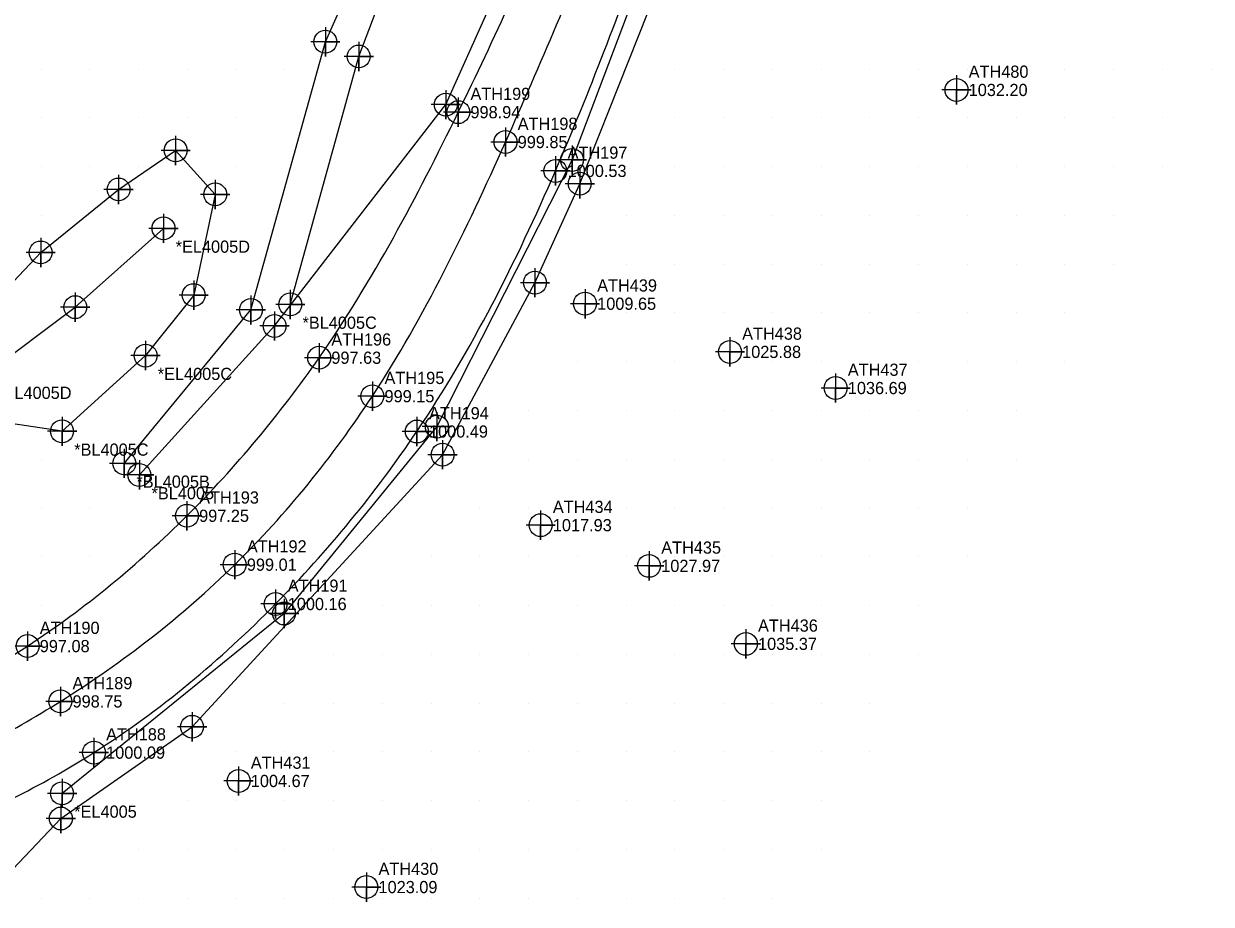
# Model space of a CAD drawing. Extents: x 1116680 to 1117499, y 661040 to 661703.
# Drawn here: x 1117186.4 to 1117430, y 661368.7 to 661549.3 of the extents above; entities that cross this region are included whole.
import ezdxf

# ---------------------------------------------------------------- set-up
doc = ezdxf.new("R2010")
doc.units = 0
for name, color, linetype in [('Exist DTM Breakline', 7, 'Continuous'), ('Exist DTM Breakline Cogo Comment', 7, 'Continuous'), ('Exist DTM Breakline Cogo Point CELL', 7, 'Continuous'), ('Exist DTM Crownline', 7, 'Continuous'), ('Exist DTM Crownline Cogo Elevation', 7, 'Continuous'), ('Exist DTM Crownline Cogo Number', 7, 'Continuous'), ('Exist DTM Crownline Cogo Point CELL', 7, 'Continuous'), ('Exist DTM QL2 LIDAR Elevation Point', 7, 'Continuous'), ('Exist DTM Regular Point CELL', 7, 'Continuous'), ('Exist DTM Regular Point Cogo Elevation', 7, 'Continuous'), ('Exist DTM Regular Point Cogo Number', 7, 'Continuous'), ('Exist Roads EOP', 7, 'Continuous'), ('Exist Roads EOP Cogo Elevation', 7, 'Continuous'), ('Exist Roads EOP Cogo Number', 7, 'Continuous'), ('Exist Roads EOP Cogo Point CELL', 7, 'Continuous')]:
    doc.layers.add(name, color=color, linetype=linetype)

msp = doc.modelspace()

# ---------------------------------------------------------------- linework, layer by layer
at = {"layer": 'Exist DTM Breakline'}
msp.add_line((1117194.27, 661465.73), (1117211.404, 661481.256), dxfattribs=at)
for points in [[(1117207.028, 661459.166), (1117233.018, 661490.613), (1117248.28, 661545.62), (1117268.093, 661590.069), (1117298.919, 661648.887), (1117319.378, 661676.709)], [(1117241.093, 661491.753), (1117255.131, 661542.605), (1117272.944, 661589.509), (1117306.544, 661644.722), (1117324.4, 661675.172)], [(1117210.127, 661456.793), (1117237.863, 661487.331), (1117272.992, 661532.718), (1117293.41, 661578.363), (1117331.106, 661672.763)], [(1117351.58, 661662.175), (1117339.299, 661629.132), (1117316.671, 661568.431), (1117298.876, 661521.377), (1117271.145, 661466.692), (1117239.817, 661428.377), (1117194.27, 661391.492)], [(1117161.696, 661291.017), (1117168.482, 661312.597), (1117176.266, 661342.559), (1117182.941, 661374.652), (1117194.026, 661386.336), (1117220.943, 661405.14), (1117272.33, 661460.939), (1117291.277, 661496.211), (1117300.472, 661516.498), (1117320.583, 661567.148), (1117342.592, 661626.703), (1117356.346, 661660.105)], [(1117194.27, 661465.73), (1117171.77, 661469.09), (1117169.6, 661480.945), (1117189.888, 661502.41), (1117205.863, 661515.329), (1117217.572, 661523.34), (1117225.692, 661514.312), (1117221.27, 661493.665), (1117211.404, 661481.256)], [(1117178.472, 661477.376), (1117196.976, 661491.194), (1117215.079, 661507.353)]]:
    msp.add_lwpolyline(points, dxfattribs=at)
at = {"layer": 'Exist DTM Breakline Cogo Point CELL'}
for points in [[(1117248.28, 661548.62), (1117248.28, 661542.62), (1117248.28, 661545.62), (1117251.28, 661545.62), (1117245.28, 661545.62)], [(1117255.131, 661545.605), (1117255.131, 661539.605), (1117255.131, 661542.605), (1117258.131, 661542.605), (1117252.131, 661542.605)], [(1117272.992, 661535.718), (1117272.992, 661529.718), (1117272.992, 661532.718), (1117275.992, 661532.718), (1117269.992, 661532.718)], [(1117217.572, 661526.34), (1117217.572, 661520.34), (1117217.572, 661523.34), (1117220.572, 661523.34), (1117214.572, 661523.34)], [(1117298.876, 661524.377), (1117298.876, 661518.377), (1117298.876, 661521.377), (1117301.876, 661521.377), (1117295.876, 661521.377)], [(1117205.863, 661518.329), (1117205.863, 661512.329), (1117205.863, 661515.329), (1117208.863, 661515.329), (1117202.863, 661515.329)], [(1117300.472, 661519.498), (1117300.472, 661513.498), (1117300.472, 661516.498), (1117303.472, 661516.498), (1117297.472, 661516.498)], [(1117225.692, 661517.312), (1117225.692, 661511.312), (1117225.692, 661514.312), (1117228.692, 661514.312), (1117222.692, 661514.312)], [(1117215.079, 661510.353), (1117215.079, 661504.353), (1117215.079, 661507.353), (1117218.079, 661507.353), (1117212.079, 661507.353)], [(1117189.888, 661505.41), (1117189.888, 661499.41), (1117189.888, 661502.41), (1117192.888, 661502.41), (1117186.888, 661502.41)], [(1117291.277, 661499.211), (1117291.277, 661493.211), (1117291.277, 661496.211), (1117294.277, 661496.211), (1117288.277, 661496.211)], [(1117221.27, 661496.665), (1117221.27, 661490.665), (1117221.27, 661493.665), (1117224.27, 661493.665), (1117218.27, 661493.665)], [(1117196.976, 661494.194), (1117196.976, 661488.194), (1117196.976, 661491.194), (1117199.976, 661491.194), (1117193.976, 661491.194)], [(1117233.018, 661493.613), (1117233.018, 661487.613), (1117233.018, 661490.613), (1117236.018, 661490.613), (1117230.018, 661490.613)], [(1117241.093, 661494.753), (1117241.093, 661488.753), (1117241.093, 661491.753), (1117244.093, 661491.753), (1117238.093, 661491.753)], [(1117237.863, 661490.331), (1117237.863, 661484.331), (1117237.863, 661487.331), (1117240.863, 661487.331), (1117234.863, 661487.331)], [(1117211.404, 661484.256), (1117211.404, 661478.256), (1117211.404, 661481.256), (1117214.404, 661481.256), (1117208.404, 661481.256)], [(1117194.27, 661468.73), (1117194.27, 661462.73), (1117194.27, 661465.73), (1117197.27, 661465.73), (1117191.27, 661465.73)], [(1117271.145, 661469.692), (1117271.145, 661463.692), (1117271.145, 661466.692), (1117274.145, 661466.692), (1117268.145, 661466.692)], [(1117272.33, 661463.939), (1117272.33, 661457.939), (1117272.33, 661460.939), (1117275.33, 661460.939), (1117269.33, 661460.939)], [(1117207.028, 661462.166), (1117207.028, 661456.166), (1117207.028, 661459.166), (1117210.028, 661459.166), (1117204.028, 661459.166)], [(1117210.127, 661459.793), (1117210.127, 661453.793), (1117210.127, 661456.793), (1117213.127, 661456.793), (1117207.127, 661456.793)], [(1117239.817, 661431.377), (1117239.817, 661425.377), (1117239.817, 661428.377), (1117242.817, 661428.377), (1117236.817, 661428.377)], [(1117220.943, 661408.14), (1117220.943, 661402.14), (1117220.943, 661405.14), (1117223.943, 661405.14), (1117217.943, 661405.14)], [(1117194.27, 661394.492), (1117194.27, 661388.492), (1117194.27, 661391.492), (1117197.27, 661391.492), (1117191.27, 661391.492)], [(1117194.026, 661389.336), (1117194.026, 661383.336), (1117194.026, 661386.336), (1117197.026, 661386.336), (1117191.026, 661386.336)]]:
    msp.add_lwpolyline(points, dxfattribs=at)
for centre in [(1117248.28, 661545.62), (1117255.131, 661542.605), (1117272.992, 661532.718), (1117217.572, 661523.34), (1117298.876, 661521.377), (1117205.863, 661515.329), (1117300.472, 661516.498), (1117225.692, 661514.312), (1117215.079, 661507.353), (1117189.888, 661502.41), (1117291.277, 661496.211), (1117221.27, 661493.665), (1117196.976, 661491.194), (1117241.093, 661491.753), (1117233.018, 661490.613), (1117237.863, 661487.331), (1117211.404, 661481.256), (1117271.145, 661466.692), (1117194.27, 661465.73), (1117207.028, 661459.166), (1117272.33, 661460.939), (1117210.127, 661456.793), (1117239.817, 661428.377), (1117220.943, 661405.14), (1117194.27, 661391.492), (1117194.026, 661386.336)]:
    msp.add_circle(centre, 2.344, dxfattribs=at)
at = {"layer": 'Exist DTM Crownline'}
msp.add_spline([(1117128.608, 661382.881), (1117161.083, 661393.544), (1117193.928, 661410.345), (1117229.679, 661438.384), (1117257.918, 661472.931), (1117285.234, 661525.056), (1117305.735, 661573.245), (1117329.129, 661633.315)], degree=3, dxfattribs=at)
at = {"layer": 'Exist DTM Crownline Cogo Point CELL'}
for points in [[(1117285.234, 661528.056), (1117285.234, 661522.056), (1117285.234, 661525.056), (1117288.234, 661525.056), (1117282.234, 661525.056)], [(1117257.918, 661475.931), (1117257.918, 661469.931), (1117257.918, 661472.931), (1117260.918, 661472.931), (1117254.918, 661472.931)], [(1117229.679, 661441.384), (1117229.679, 661435.384), (1117229.679, 661438.384), (1117232.679, 661438.384), (1117226.679, 661438.384)], [(1117193.928, 661413.345), (1117193.928, 661407.345), (1117193.928, 661410.345), (1117196.928, 661410.345), (1117190.928, 661410.345)]]:
    msp.add_lwpolyline(points, dxfattribs=at)
for centre in [(1117285.234, 661525.056), (1117257.918, 661472.931), (1117229.679, 661438.384), (1117193.928, 661410.345)]:
    msp.add_circle(centre, 2.344, dxfattribs=at)
at = {"layer": 'Exist DTM QL2 LIDAR Elevation Point'}
for p, q in [((1117190, 661540), (1117190, 661540)), ((1117200, 661540), (1117200, 661540)), ((1117210, 661540), (1117210, 661540)), ((1117220, 661540), (1117220, 661540)), ((1117230, 661540), (1117230, 661540)), ((1117240, 661540), (1117240, 661540)), ((1117320, 661540), (1117320, 661540)), ((1117330, 661540), (1117330, 661540)), ((1117340, 661540), (1117340, 661540)), ((1117350, 661540), (1117350, 661540)), ((1117360, 661540), (1117360, 661540)), ((1117370, 661540), (1117370, 661540)), ((1117380, 661540), (1117380, 661540)), ((1117390, 661540), (1117390, 661540)), ((1117400, 661540), (1117400, 661540)), ((1117410, 661540), (1117410, 661540)), ((1117420, 661540), (1117420, 661540)), ((1117430, 661540), (1117430, 661540)), ((1117190, 661530), (1117190, 661530)), ((1117200, 661530), (1117200, 661530)), ((1117210, 661530), (1117210, 661530)), ((1117220, 661530), (1117220, 661530)), ((1117230, 661530), (1117230, 661530)), ((1117320, 661530), (1117320, 661530)), ((1117330, 661530), (1117330, 661530)), ((1117340, 661530), (1117340, 661530)), ((1117350, 661530), (1117350, 661530)), ((1117360, 661530), (1117360, 661530)), ((1117370, 661530), (1117370, 661530)), ((1117380, 661530), (1117380, 661530)), ((1117390, 661530), (1117390, 661530)), ((1117400, 661530), (1117400, 661530)), ((1117410, 661530), (1117410, 661530)), ((1117420, 661530), (1117420, 661530)), ((1117190, 661520), (1117190, 661520)), ((1117200, 661520), (1117200, 661520)), ((1117210, 661520), (1117210, 661520)), ((1117230, 661520), (1117230, 661520)), ((1117310, 661520), (1117310, 661520)), ((1117320, 661520), (1117320, 661520)), ((1117330, 661520), (1117330, 661520)), ((1117340, 661520), (1117340, 661520)), ((1117350, 661520), (1117350, 661520)), ((1117360, 661520), (1117360, 661520)), ((1117370, 661520), (1117370, 661520)), ((1117380, 661520), (1117380, 661520)), ((1117390, 661520), (1117390, 661520)), ((1117400, 661520), (1117400, 661520)), ((1117410, 661520), (1117410, 661520)), ((1117420, 661520), (1117420, 661520)), ((1117190, 661510), (1117190, 661510)), ((1117310, 661510), (1117310, 661510)), ((1117320, 661510), (1117320, 661510)), ((1117330, 661510), (1117330, 661510)), ((1117340, 661510), (1117340, 661510)), ((1117350, 661510), (1117350, 661510)), ((1117360, 661510), (1117360, 661510)), ((1117370, 661510), (1117370, 661510)), ((1117380, 661510), (1117380, 661510)), ((1117390, 661510), (1117390, 661510)), ((1117400, 661510), (1117400, 661510)), ((1117410, 661510), (1117410, 661510)), ((1117310, 661500), (1117310, 661500)), ((1117320, 661500), (1117320, 661500)), ((1117330, 661500), (1117330, 661500)), ((1117340, 661500), (1117340, 661500)), ((1117350, 661500), (1117350, 661500)), ((1117360, 661500), (1117360, 661500)), ((1117370, 661500), (1117370, 661500)), ((1117380, 661500), (1117380, 661500)), ((1117390, 661500), (1117390, 661500)), ((1117400, 661500), (1117400, 661500)), ((1117410, 661500), (1117410, 661500)), ((1117310, 661490), (1117310, 661490)), ((1117320, 661490), (1117320, 661490)), ((1117330, 661490), (1117330, 661490)), ((1117340, 661490), (1117340, 661490)), ((1117350, 661490), (1117350, 661490)), ((1117360, 661490), (1117360, 661490)), ((1117370, 661490), (1117370, 661490)), ((1117380, 661490), (1117380, 661490)), ((1117390, 661490), (1117390, 661490)), ((1117400, 661490), (1117400, 661490)), ((1117300, 661480), (1117300, 661480)), ((1117310, 661480), (1117310, 661480)), ((1117320, 661480), (1117320, 661480)), ((1117330, 661480), (1117330, 661480)), ((1117340, 661480), (1117340, 661480)), ((1117350, 661480), (1117350, 661480)), ((1117360, 661480), (1117360, 661480)), ((1117370, 661480), (1117370, 661480)), ((1117380, 661480), (1117380, 661480)), ((1117390, 661480), (1117390, 661480)), ((1117400, 661480), (1117400, 661480)), ((1117290, 661470), (1117290, 661470)), ((1117300, 661470), (1117300, 661470)), ((1117310, 661470), (1117310, 661470)), ((1117320, 661470), (1117320, 661470)), ((1117330, 661470), (1117330, 661470)), ((1117340, 661470), (1117340, 661470)), ((1117350, 661470), (1117350, 661470)), ((1117360, 661470), (1117360, 661470)), ((1117370, 661470), (1117370, 661470)), ((1117380, 661470), (1117380, 661470)), ((1117390, 661470), (1117390, 661470)), ((1117190, 661460), (1117190, 661460)), ((1117290, 661460), (1117290, 661460)), ((1117300, 661460), (1117300, 661460)), ((1117310, 661460), (1117310, 661460)), ((1117320, 661460), (1117320, 661460)), ((1117330, 661460), (1117330, 661460)), ((1117340, 661460), (1117340, 661460)), ((1117350, 661460), (1117350, 661460)), ((1117360, 661460), (1117360, 661460)), ((1117370, 661460), (1117370, 661460)), ((1117380, 661460), (1117380, 661460)), ((1117390, 661460), (1117390, 661460)), ((1117190, 661450), (1117190, 661450)), ((1117200, 661450), (1117200, 661450)), ((1117280, 661450), (1117280, 661450)), ((1117290, 661450), (1117290, 661450)), ((1117300, 661450), (1117300, 661450)), ((1117310, 661450), (1117310, 661450)), ((1117320, 661450), (1117320, 661450)), ((1117330, 661450), (1117330, 661450)), ((1117340, 661450), (1117340, 661450)), ((1117350, 661450), (1117350, 661450)), ((1117360, 661450), (1117360, 661450)), ((1117370, 661450), (1117370, 661450)), ((1117380, 661450), (1117380, 661450)), ((1117190, 661440), (1117190, 661440)), ((1117200, 661440), (1117200, 661440)), ((1117270, 661440), (1117270, 661440)), ((1117280, 661440), (1117280, 661440)), ((1117290, 661440), (1117290, 661440)), ((1117300, 661440), (1117300, 661440)), ((1117310, 661440), (1117310, 661440)), ((1117320, 661440), (1117320, 661440)), ((1117330, 661440), (1117330, 661440)), ((1117340, 661440), (1117340, 661440)), ((1117350, 661440), (1117350, 661440)), ((1117360, 661440), (1117360, 661440)), ((1117370, 661440), (1117370, 661440)), ((1117380, 661440), (1117380, 661440)), ((1117190, 661430), (1117190, 661430)), ((1117260, 661430), (1117260, 661430)), ((1117270, 661430), (1117270, 661430)), ((1117280, 661430), (1117280, 661430)), ((1117290, 661430), (1117290, 661430)), ((1117300, 661430), (1117300, 661430)), ((1117310, 661430), (1117310, 661430)), ((1117320, 661430), (1117320, 661430)), ((1117330, 661430), (1117330, 661430)), ((1117340, 661430), (1117340, 661430)), ((1117350, 661430), (1117350, 661430)), ((1117360, 661430), (1117360, 661430)), ((1117370, 661430), (1117370, 661430)), ((1117250, 661420), (1117250, 661420)), ((1117260, 661420), (1117260, 661420)), ((1117270, 661420), (1117270, 661420)), ((1117280, 661420), (1117280, 661420)), ((1117290, 661420), (1117290, 661420)), ((1117300, 661420), (1117300, 661420)), ((1117310, 661420), (1117310, 661420)), ((1117320, 661420), (1117320, 661420)), ((1117330, 661420), (1117330, 661420)), ((1117340, 661420), (1117340, 661420)), ((1117350, 661420), (1117350, 661420)), ((1117360, 661420), (1117360, 661420)), ((1117370, 661420), (1117370, 661420)), ((1117240, 661410), (1117240, 661410)), ((1117250, 661410), (1117250, 661410)), ((1117260, 661410), (1117260, 661410)), ((1117270, 661410), (1117270, 661410)), ((1117280, 661410), (1117280, 661410)), ((1117290, 661410), (1117290, 661410)), ((1117300, 661410), (1117300, 661410)), ((1117310, 661410), (1117310, 661410)), ((1117320, 661410), (1117320, 661410)), ((1117330, 661410), (1117330, 661410)), ((1117340, 661410), (1117340, 661410)), ((1117350, 661410), (1117350, 661410)), ((1117360, 661410), (1117360, 661410)), ((1117230, 661400), (1117230, 661400)), ((1117240, 661400), (1117240, 661400)), ((1117250, 661400), (1117250, 661400)), ((1117260, 661400), (1117260, 661400)), ((1117270, 661400), (1117270, 661400)), ((1117280, 661400), (1117280, 661400)), ((1117290, 661400), (1117290, 661400)), ((1117300, 661400), (1117300, 661400)), ((1117310, 661400), (1117310, 661400)), ((1117320, 661400), (1117320, 661400)), ((1117330, 661400), (1117330, 661400)), ((1117340, 661400), (1117340, 661400)), ((1117350, 661400), (1117350, 661400)), ((1117360, 661400), (1117360, 661400)), ((1117220, 661390), (1117220, 661390)), ((1117230, 661390), (1117230, 661390)), ((1117240, 661390), (1117240, 661390)), ((1117250, 661390), (1117250, 661390)), ((1117260, 661390), (1117260, 661390)), ((1117270, 661390), (1117270, 661390)), ((1117280, 661390), (1117280, 661390)), ((1117290, 661390), (1117290, 661390)), ((1117300, 661390), (1117300, 661390)), ((1117310, 661390), (1117310, 661390)), ((1117320, 661390), (1117320, 661390)), ((1117330, 661390), (1117330, 661390)), ((1117340, 661390), (1117340, 661390)), ((1117350, 661390), (1117350, 661390)), ((1117210, 661380), (1117210, 661380)), ((1117220, 661380), (1117220, 661380)), ((1117230, 661380), (1117230, 661380)), ((1117240, 661380), (1117240, 661380)), ((1117250, 661380), (1117250, 661380)), ((1117260, 661380), (1117260, 661380)), ((1117270, 661380), (1117270, 661380)), ((1117280, 661380), (1117280, 661380)), ((1117290, 661380), (1117290, 661380)), ((1117300, 661380), (1117300, 661380)), ((1117310, 661380), (1117310, 661380)), ((1117320, 661380), (1117320, 661380)), ((1117330, 661380), (1117330, 661380)), ((1117340, 661380), (1117340, 661380)), ((1117350, 661380), (1117350, 661380)), ((1117190, 661370), (1117190, 661370)), ((1117200, 661370), (1117200, 661370)), ((1117210, 661370), (1117210, 661370)), ((1117220, 661370), (1117220, 661370)), ((1117230, 661370), (1117230, 661370)), ((1117240, 661370), (1117240, 661370)), ((1117250, 661370), (1117250, 661370)), ((1117260, 661370), (1117260, 661370)), ((1117270, 661370), (1117270, 661370)), ((1117280, 661370), (1117280, 661370)), ((1117290, 661370), (1117290, 661370)), ((1117300, 661370), (1117300, 661370)), ((1117310, 661370), (1117310, 661370)), ((1117320, 661370), (1117320, 661370)), ((1117330, 661370), (1117330, 661370)), ((1117340, 661370), (1117340, 661370))]:
    msp.add_line(p, q, dxfattribs=at)
at = {"layer": 'Exist DTM Regular Point CELL'}
for points in [[(1117377.744, 661538.736), (1117377.744, 661532.736), (1117377.744, 661535.736), (1117380.744, 661535.736), (1117374.744, 661535.736)], [(1117301.542, 661494.899), (1117301.542, 661488.899), (1117301.542, 661491.899), (1117304.542, 661491.899), (1117298.542, 661491.899)], [(1117331.279, 661485.017), (1117331.279, 661479.017), (1117331.279, 661482.017), (1117334.279, 661482.017), (1117328.279, 661482.017)], [(1117352.951, 661477.61), (1117352.951, 661471.61), (1117352.951, 661474.61), (1117355.951, 661474.61), (1117349.951, 661474.61)], [(1117292.445, 661449.487), (1117292.445, 661443.487), (1117292.445, 661446.487), (1117295.445, 661446.487), (1117289.445, 661446.487)], [(1117314.679, 661441.139), (1117314.679, 661435.139), (1117314.679, 661438.139), (1117317.679, 661438.139), (1117311.679, 661438.139)], [(1117334.535, 661425.143), (1117334.535, 661419.143), (1117334.535, 661422.143), (1117337.535, 661422.143), (1117331.535, 661422.143)], [(1117230.487, 661397.029), (1117230.487, 661391.029), (1117230.487, 661394.029), (1117233.487, 661394.029), (1117227.487, 661394.029)], [(1117256.688, 661375.272), (1117256.688, 661369.272), (1117256.688, 661372.272), (1117259.688, 661372.272), (1117253.688, 661372.272)]]:
    msp.add_lwpolyline(points, dxfattribs=at)
for centre in [(1117377.744, 661535.736), (1117301.542, 661491.899), (1117331.279, 661482.017), (1117352.951, 661474.61), (1117292.445, 661446.487), (1117314.679, 661438.139), (1117334.535, 661422.143), (1117230.487, 661394.029), (1117256.688, 661372.272)]:
    msp.add_circle(centre, 2.344, dxfattribs=at)
at = {"layer": 'Exist Roads EOP'}
for points in [[(1117102.286, 661387.333), (1117126.621, 661394.057), (1117156.418, 661404.979), (1117187.204, 661421.689), (1117219.891, 661448.41), (1117247.012, 661480.823), (1117275.546, 661531.18), (1117296.661, 661577.27), (1117320.803, 661635.676)], [(1117131.334, 661372.856), (1117166.321, 661382.847), (1117200.815, 661399.841), (1117238.067, 661430.322), (1117267.048, 661465.689), (1117295.472, 661519.132), (1117314.821, 661568.418)]]:
    msp.add_spline(points, degree=3, dxfattribs=at)
at = {"layer": 'Exist Roads EOP Cogo Point CELL'}
for points in [[(1117275.546, 661534.18), (1117275.546, 661528.18), (1117275.546, 661531.18), (1117278.546, 661531.18), (1117272.546, 661531.18)], [(1117295.472, 661522.132), (1117295.472, 661516.132), (1117295.472, 661519.132), (1117298.472, 661519.132), (1117292.472, 661519.132)], [(1117247.012, 661483.823), (1117247.012, 661477.823), (1117247.012, 661480.823), (1117250.012, 661480.823), (1117244.012, 661480.823)], [(1117267.048, 661468.689), (1117267.048, 661462.689), (1117267.048, 661465.689), (1117270.048, 661465.689), (1117264.048, 661465.689)], [(1117219.891, 661451.41), (1117219.891, 661445.41), (1117219.891, 661448.41), (1117222.891, 661448.41), (1117216.891, 661448.41)], [(1117238.067, 661433.322), (1117238.067, 661427.322), (1117238.067, 661430.322), (1117241.067, 661430.322), (1117235.067, 661430.322)], [(1117187.204, 661424.689), (1117187.204, 661418.689), (1117187.204, 661421.689), (1117190.204, 661421.689), (1117184.204, 661421.689)], [(1117200.815, 661402.841), (1117200.815, 661396.841), (1117200.815, 661399.841), (1117203.815, 661399.841), (1117197.815, 661399.841)]]:
    msp.add_lwpolyline(points, dxfattribs=at)
for centre in [(1117275.546, 661531.18), (1117295.472, 661519.132), (1117247.012, 661480.823), (1117267.048, 661465.689), (1117219.891, 661448.41), (1117238.067, 661430.322), (1117187.204, 661421.689), (1117200.815, 661399.841)]:
    msp.add_circle(centre, 2.344, dxfattribs=at)

# ---------------------------------------------------------------- texts
at = {"layer": 'Exist DTM Breakline Cogo Comment'}
for s, p in [('*EL4005D', (1117217.579, 661502.353)), ('*BL4005C', (1117243.593, 661486.753)), ('*EL4005C', (1117213.904, 661476.256)), ('*BL4005D', (1117180.972, 661472.376)), ('*BL4005C', (1117196.77, 661460.73)), ('*BL4005B', (1117209.528, 661454.166)), ('*BL4005', (1117212.627, 661451.793)), ('*EL4005', (1117196.77, 661386.492))]:
    msp.add_text(s, height=2.5, dxfattribs=at).set_placement(p)
at = {"layer": 'Exist DTM Crownline Cogo Elevation'}
for s, p in [('999.85', (1117287.734, 661523.806)), ('999.15', (1117260.418, 661471.681)), ('999.01', (1117232.179, 661437.134)), ('998.75', (1117196.428, 661409.095))]:
    msp.add_text(s, height=2.5, dxfattribs=at).set_placement(p)
at = {"layer": 'Exist DTM Crownline Cogo Number'}
for s, p in [('ATH198', (1117287.734, 661527.556)), ('ATH195', (1117260.418, 661475.431)), ('ATH192', (1117232.179, 661440.884)), ('ATH189', (1117196.428, 661412.845))]:
    msp.add_text(s, height=2.5, dxfattribs=at).set_placement(p)
at = {"layer": 'Exist DTM Regular Point Cogo Elevation'}
for s, p in [('1032.20', (1117380.244, 661534.486)), ('1009.65', (1117304.042, 661490.649)), ('1025.88', (1117333.779, 661480.767)), ('1036.69', (1117355.451, 661473.36)), ('1017.93', (1117294.945, 661445.237)), ('1027.97', (1117317.179, 661436.889)), ('1035.37', (1117337.035, 661420.893)), ('1004.67', (1117232.987, 661392.779)), ('1023.09', (1117259.188, 661371.022))]:
    msp.add_text(s, height=2.5, dxfattribs=at).set_placement(p)
at = {"layer": 'Exist DTM Regular Point Cogo Number'}
for s, p in [('ATH480', (1117380.244, 661538.236)), ('ATH439', (1117304.042, 661494.399)), ('ATH438', (1117333.779, 661484.517)), ('ATH437', (1117355.451, 661477.11)), ('ATH434', (1117294.945, 661448.987)), ('ATH435', (1117317.179, 661440.639)), ('ATH436', (1117337.035, 661424.643)), ('ATH431', (1117232.987, 661396.529)), ('ATH430', (1117259.188, 661374.772))]:
    msp.add_text(s, height=2.5, dxfattribs=at).set_placement(p)
at = {"layer": 'Exist Roads EOP Cogo Elevation'}
for s, p in [('998.94', (1117278.046, 661529.93)), ('1000.53', (1117297.972, 661517.882)), ('997.63', (1117249.512, 661479.573)), ('1000.49', (1117269.548, 661464.439)), ('997.25', (1117222.391, 661447.16)), ('1000.16', (1117240.567, 661429.072)), ('997.08', (1117189.704, 661420.439)), ('1000.09', (1117203.315, 661398.591))]:
    msp.add_text(s, height=2.5, dxfattribs=at).set_placement(p)
at = {"layer": 'Exist Roads EOP Cogo Number'}
for s, p in [('ATH199', (1117278.046, 661533.68)), ('ATH197', (1117297.972, 661521.632)), ('ATH196', (1117249.512, 661483.323)), ('ATH194', (1117269.548, 661468.189)), ('ATH193', (1117222.391, 661450.91)), ('ATH191', (1117240.567, 661432.822)), ('ATH190', (1117189.704, 661424.189)), ('ATH188', (1117203.315, 661402.341))]:
    msp.add_text(s, height=2.5, dxfattribs=at).set_placement(p)

doc.saveas('drawing.dxf')
